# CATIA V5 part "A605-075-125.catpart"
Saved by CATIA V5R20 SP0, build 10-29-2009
Part number: A605-075-125
Source: Unknown
Property "A": "45.000"
Property "ARTICLENO": "A605-075-125"
Property "BOMINFO": "A605-075-125"
Property "CODE": "A605-075-125"
Property "D": "9.000"
Property "FORM": "C"
Property "L": "125.000"
Property "L1": "95.000"
Property "LINA": "A605-075-125"
Property "NB": "A605-075-125"
Property "NBSYN": "$CODE."
Property "NN": "A605"
Property "NT": "Wear Plates, self-lubricating"
Property "SCREW": "4*M8X16"
Property "SUPPLIER": "CF"
Property "W": "75.000"
Bounding box of the stored display mesh (mm): x -75 to 0, y 0 to 5, z -125 to 0
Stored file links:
  C:\Users\Utente\Desktop\3D files A605\A605-075-125.catpart
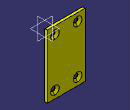
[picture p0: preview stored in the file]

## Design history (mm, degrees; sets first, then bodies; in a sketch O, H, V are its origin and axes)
Body1 "Geometry.1" (main body)
  Solid1 "A605-075-125.catpart": solid without history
